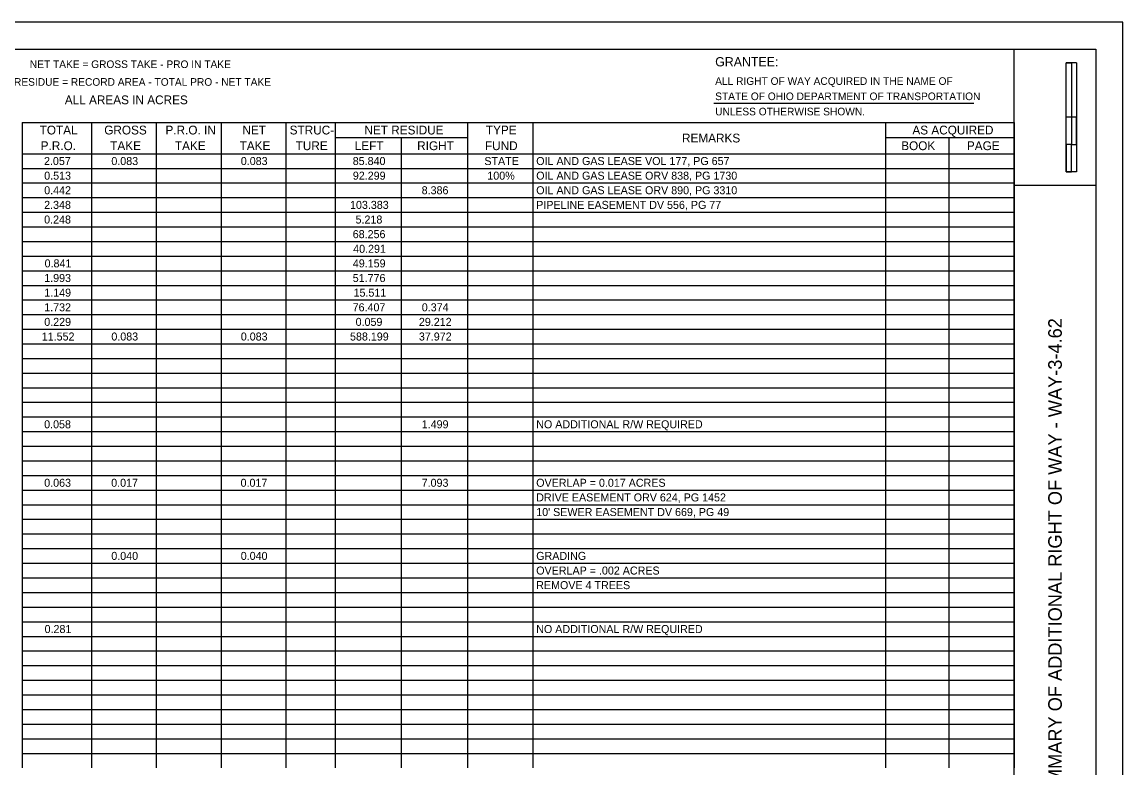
# Model space of a CAD drawing. Extents: x 0 to 34, y 0 to 22.
# Drawn here: x 13.75 to 34, y 8.29 to 22 of the extents above; entities that cross this region are included whole.
import ezdxf

# ---------------------------------------------------------------- set-up
doc = ezdxf.new("R2010")
doc.units = 0
for name, color, linetype in [('Default', 7, 'Continuous'), ('SH_Border', 7, 'Continuous'), ('SH_Cut_Line', 7, 'Continuous'), ('SH_Data', 7, 'Continuous'), ('SH_Text', 7, 'Continuous')]:
    doc.layers.add(name, color=color, linetype=linetype)

msp = doc.modelspace()

# ---------------------------------------------------------------- linework, layer by layer
at = {"layer": 'Default'}
for p, q in [((13.749, 20.156), (16.219, 20.156)), ((13.749, 20.156), (13.749, 15.817)), ((15.029, 20.156), (15.029, 15.817)), ((16.219, 20.156), (30.797, 20.156)), ((16.219, 20.156), (16.219, 15.817)), ((17.409, 20.156), (17.409, 15.817)), ((18.599, 20.156), (18.599, 15.817)), ((19.508, 20.156), (19.508, 15.817)), ((21.94, 20.156), (21.94, 15.817)), ((23.143, 20.156), (23.143, 15.817)), ((29.632, 20.156), (29.632, 15.817)), ((30.797, 20.156), (32, 20.156)), ((32, 20.156), (32, 15.817)), ((19.508, 19.875), (21.94, 19.875)), ((20.724, 19.875), (20.724, 15.817)), ((29.632, 19.875), (30.797, 19.875)), ((30.797, 19.875), (32, 19.875)), ((30.797, 19.875), (30.797, 15.817)), ((13.749, 19.58), (16.219, 19.58)), ((16.219, 19.58), (30.797, 19.58)), ((30.797, 19.58), (32, 19.58)), ((13.749, 19.311), (16.219, 19.311)), ((16.219, 19.311), (30.797, 19.311)), ((30.797, 19.311), (32, 19.311)), ((13.749, 19.043), (16.219, 19.043)), ((16.219, 19.043), (30.797, 19.043)), ((30.797, 19.043), (32, 19.043)), ((13.749, 18.774), (16.219, 18.774)), ((16.219, 18.774), (30.797, 18.774)), ((30.797, 18.774), (32, 18.774)), ((13.749, 18.505), (16.219, 18.505)), ((16.219, 18.505), (30.797, 18.505)), ((30.797, 18.505), (32, 18.505)), ((13.749, 18.236), (16.219, 18.236)), ((16.219, 18.236), (30.797, 18.236)), ((30.797, 18.236), (32, 18.236)), ((13.749, 17.967), (16.219, 17.967)), ((16.219, 17.967), (30.797, 17.967)), ((30.797, 17.967), (32, 17.967)), ((13.749, 17.699), (16.219, 17.699)), ((16.219, 17.699), (30.797, 17.699)), ((30.797, 17.699), (32, 17.699)), ((13.749, 17.43), (16.219, 17.43)), ((16.219, 17.43), (30.797, 17.43)), ((30.797, 17.43), (32, 17.43)), ((13.749, 17.161), (16.219, 17.161)), ((16.219, 17.161), (30.797, 17.161)), ((30.797, 17.161), (32, 17.161)), ((13.749, 16.892), (16.219, 16.892)), ((16.219, 16.892), (30.797, 16.892)), ((30.797, 16.892), (32, 16.892)), ((13.749, 16.624), (16.219, 16.624)), ((16.219, 16.624), (30.797, 16.624)), ((30.797, 16.624), (32, 16.624)), ((13.749, 16.355), (16.219, 16.355)), ((16.219, 16.355), (21.94, 16.355)), ((21.94, 16.355), (30.797, 16.355)), ((30.797, 16.355), (32, 16.355)), ((13.749, 16.086), (16.219, 16.086)), ((16.219, 16.086), (30.797, 16.086)), ((30.797, 16.086), (32, 16.086)), ((13.749, 15.817), (16.219, 15.817)), ((13.749, 15.817), (13.749, 15.548)), ((15.029, 15.817), (15.029, 15.548)), ((16.219, 15.817), (30.797, 15.817)), ((16.219, 15.817), (16.219, 15.548)), ((17.409, 15.817), (17.409, 15.548)), ((18.599, 15.817), (18.599, 15.548)), ((19.508, 15.817), (19.508, 15.548)), ((20.724, 15.817), (20.724, 15.548)), ((21.94, 15.817), (21.94, 15.548)), ((23.143, 15.817), (23.143, 15.548)), ((29.632, 15.817), (29.632, 15.548)), ((30.797, 15.817), (32, 15.817)), ((30.797, 15.817), (30.797, 15.548)), ((32, 15.817), (32, 15.548)), ((13.749, 15.548), (16.219, 15.548)), ((13.749, 15.548), (13.749, 15.28)), ((15.029, 15.548), (15.029, 15.28)), ((16.219, 15.548), (30.797, 15.548)), ((16.219, 15.548), (16.219, 15.28)), ((17.409, 15.548), (17.409, 15.28)), ((18.599, 15.548), (18.599, 15.28)), ((19.508, 15.548), (19.508, 15.28)), ((20.724, 15.548), (20.724, 15.28)), ((21.94, 15.548), (21.94, 15.28)), ((23.143, 15.548), (23.143, 15.28)), ((29.632, 15.548), (29.632, 15.28)), ((30.797, 15.548), (32, 15.548)), ((30.797, 15.548), (30.797, 15.28)), ((32, 15.548), (32, 15.28)), ((13.749, 15.28), (16.219, 15.28)), ((13.749, 15.28), (13.749, 15.011)), ((15.029, 15.28), (15.029, 15.011)), ((16.219, 15.28), (30.797, 15.28)), ((16.219, 15.28), (16.219, 15.011)), ((17.409, 15.28), (17.409, 15.011)), ((18.599, 15.28), (18.599, 15.011)), ((19.508, 15.28), (19.508, 15.011)), ((20.724, 15.28), (20.724, 15.011)), ((21.94, 15.28), (21.94, 15.011)), ((23.143, 15.28), (23.143, 15.011)), ((29.632, 15.28), (29.632, 15.011)), ((30.797, 15.28), (32, 15.28)), ((30.797, 15.28), (30.797, 15.011)), ((32, 15.28), (32, 15.011)), ((13.749, 15.011), (16.219, 15.011)), ((13.749, 15.011), (13.749, 14.473)), ((15.029, 15.011), (15.029, 14.473)), ((16.219, 15.011), (30.797, 15.011)), ((16.219, 15.011), (16.219, 14.473)), ((17.409, 15.011), (17.409, 14.473)), ((18.599, 15.011), (18.599, 14.473)), ((19.508, 15.011), (19.508, 14.473)), ((20.724, 15.011), (20.724, 14.473)), ((21.94, 15.011), (21.94, 14.473)), ((23.143, 15.011), (23.143, 14.473)), ((29.632, 15.011), (29.632, 14.473)), ((30.797, 15.011), (32, 15.011)), ((30.797, 15.011), (30.797, 14.473)), ((32, 15.011), (32, 14.473)), ((13.749, 14.742), (16.219, 14.742)), ((16.219, 14.742), (30.797, 14.742)), ((30.797, 14.742), (32, 14.742)), ((13.749, 14.473), (16.219, 14.473)), ((13.749, 14.473), (13.749, 14.205)), ((15.029, 14.473), (15.029, 14.205)), ((16.219, 14.473), (30.797, 14.473)), ((16.219, 14.473), (16.219, 14.205)), ((17.409, 14.473), (17.409, 14.205)), ((18.599, 14.473), (18.599, 14.205)), ((19.508, 14.473), (19.508, 14.205)), ((20.724, 14.473), (20.724, 14.205)), ((21.94, 14.473), (21.94, 14.205)), ((23.143, 14.473), (23.143, 14.205)), ((29.632, 14.473), (29.632, 14.205)), ((30.797, 14.473), (32, 14.473)), ((30.797, 14.473), (30.797, 14.205)), ((32, 14.473), (32, 14.205)), ((13.749, 14.205), (16.219, 14.205)), ((13.749, 14.205), (13.749, 9.635)), ((15.029, 14.205), (15.029, 9.635)), ((16.219, 14.205), (30.797, 14.205)), ((16.219, 14.205), (16.219, 9.635)), ((17.409, 14.205), (17.409, 9.635)), ((18.599, 14.205), (18.599, 9.635)), ((19.508, 14.205), (19.508, 9.635)), ((20.724, 14.205), (20.724, 9.635)), ((21.94, 14.205), (21.94, 9.635)), ((23.143, 14.205), (23.143, 9.635)), ((29.632, 14.205), (29.632, 9.635)), ((30.797, 14.205), (32, 14.205)), ((30.797, 14.205), (30.797, 9.635)), ((32, 14.205), (32, 9.635)), ((13.749, 13.936), (16.219, 13.936)), ((16.219, 13.936), (30.797, 13.936)), ((30.797, 13.936), (32, 13.936)), ((13.749, 13.667), (16.219, 13.667)), ((16.219, 13.667), (30.797, 13.667)), ((30.797, 13.667), (32, 13.667)), ((13.749, 13.398), (16.219, 13.398)), ((16.219, 13.398), (30.797, 13.398)), ((30.797, 13.398), (32, 13.398)), ((13.749, 13.129), (16.219, 13.129)), ((16.219, 13.129), (30.797, 13.129)), ((30.797, 13.129), (32, 13.129)), ((13.749, 12.861), (16.219, 12.861)), ((16.219, 12.861), (30.797, 12.861)), ((30.797, 12.861), (32, 12.861)), ((13.749, 12.592), (16.219, 12.592)), ((16.219, 12.592), (30.797, 12.592)), ((30.797, 12.592), (32, 12.592)), ((13.749, 12.323), (16.219, 12.323)), ((16.219, 12.323), (30.797, 12.323)), ((30.797, 12.323), (32, 12.323)), ((13.749, 12.054), (16.219, 12.054)), ((16.219, 12.054), (30.797, 12.054)), ((30.797, 12.054), (32, 12.054)), ((13.749, 11.786), (16.219, 11.786)), ((16.219, 11.786), (30.797, 11.786)), ((30.797, 11.786), (32, 11.786)), ((13.749, 11.517), (16.219, 11.517)), ((16.219, 11.517), (30.797, 11.517)), ((30.797, 11.517), (32, 11.517)), ((13.749, 11.248), (16.219, 11.248)), ((16.219, 11.248), (30.797, 11.248)), ((30.797, 11.248), (32, 11.248)), ((13.749, 10.979), (16.219, 10.979)), ((16.219, 10.979), (30.797, 10.979)), ((30.797, 10.979), (32, 10.979)), ((13.749, 10.71), (16.219, 10.71)), ((16.219, 10.71), (30.797, 10.71)), ((30.797, 10.71), (32, 10.71)), ((13.749, 10.442), (16.219, 10.442)), ((16.219, 10.442), (30.797, 10.442)), ((30.797, 10.442), (32, 10.442)), ((13.749, 10.173), (16.219, 10.173)), ((16.219, 10.173), (30.797, 10.173)), ((30.797, 10.173), (32, 10.173)), ((13.749, 9.904), (16.219, 9.904)), ((16.219, 9.904), (30.797, 9.904)), ((30.797, 9.904), (32, 9.904)), ((13.749, 9.635), (16.219, 9.635)), ((13.749, 9.635), (13.749, 9.367)), ((15.029, 9.635), (15.029, 9.367)), ((16.219, 9.635), (30.797, 9.635)), ((16.219, 9.635), (16.219, 9.367)), ((17.409, 9.635), (17.409, 9.367)), ((18.599, 9.635), (18.599, 9.367)), ((19.508, 9.635), (19.508, 9.367)), ((20.724, 9.635), (20.724, 9.367)), ((21.94, 9.635), (21.94, 9.367)), ((23.143, 9.635), (23.143, 9.367)), ((29.632, 9.635), (29.632, 9.367)), ((30.797, 9.635), (32, 9.635)), ((30.797, 9.635), (30.797, 9.367)), ((32, 9.635), (32, 9.367)), ((13.749, 9.367), (16.219, 9.367)), ((13.749, 9.367), (13.749, 9.098)), ((15.029, 9.367), (15.029, 9.098)), ((16.219, 9.367), (30.797, 9.367)), ((16.219, 9.367), (16.219, 9.098)), ((17.409, 9.367), (17.409, 9.098)), ((18.599, 9.367), (18.599, 9.098)), ((19.508, 9.367), (19.508, 9.098)), ((20.724, 9.367), (20.724, 9.098)), ((21.94, 9.367), (21.94, 9.098)), ((23.143, 9.367), (23.143, 9.098)), ((29.632, 9.367), (29.632, 9.098)), ((30.797, 9.367), (32, 9.367)), ((30.797, 9.367), (30.797, 9.098)), ((32, 9.367), (32, 9.098)), ((13.749, 9.098), (16.219, 9.098)), ((13.749, 9.098), (13.749, 8.291)), ((15.029, 9.098), (15.029, 8.291)), ((16.219, 9.098), (30.797, 9.098)), ((16.219, 9.098), (16.219, 8.291)), ((17.409, 9.098), (17.409, 8.291)), ((18.599, 9.098), (18.599, 8.291)), ((19.508, 9.098), (19.508, 8.291)), ((20.724, 9.098), (20.724, 8.291)), ((21.94, 9.098), (21.94, 8.291)), ((23.143, 9.098), (23.143, 8.291)), ((29.632, 9.098), (29.632, 8.291)), ((30.797, 9.098), (32, 9.098)), ((30.797, 9.098), (30.797, 8.291)), ((32, 9.098), (32, 8.291)), ((13.749, 8.829), (16.219, 8.829)), ((16.219, 8.829), (30.797, 8.829)), ((30.797, 8.829), (32, 8.829)), ((13.749, 8.56), (16.219, 8.56)), ((16.219, 8.56), (30.797, 8.56)), ((30.797, 8.56), (32, 8.56))]:
    msp.add_line(p, q, dxfattribs=at)
at = {"layer": 'SH_Border'}
for p, q in [((32, 0.5), (32, 21.5)), ((32, 19), (33.5, 19))]:
    msp.add_line(p, q, dxfattribs=at)
msp.add_lwpolyline([(1.5, 21.5), (33.5, 21.5), (33.5, 0.5), (1.5, 0.5)], close=True, dxfattribs=at)
at = {"layer": 'SH_Cut_Line'}
msp.add_lwpolyline([(0, 0), (34, 0), (34, 22), (0, 22)], close=True, dxfattribs=at)
at = {"layer": 'SH_Data'}
for p, q in [((32.957, 19.25), (32.957, 21.25)), ((33.144, 21.25), (32.957, 21.25)), ((32.957, 20.25), (32.957, 21.25)), ((32.957, 21.25), (33.05, 21.25)), ((33.05, 21.25), (33.051, 21.25)), ((33.051, 21.25), (33.051, 20.25)), ((33.144, 21.25), (33.144, 19.25)), ((33.051, 20.25), (32.957, 20.25)), ((33.143, 20.25), (33.05, 20.25)), ((33.05, 20.25), (33.05, 19.75)), ((33.143, 19.75), (33.143, 20.25)), ((33.05, 19.75), (32.957, 19.75)), ((32.957, 19.75), (32.957, 19.25)), ((33.05, 19.75), (33.143, 19.75)), ((33.05, 19.25), (33.05, 19.75)), ((33.144, 19.25), (32.957, 19.25)), ((32.957, 19.25), (33.05, 19.25))]:
    msp.add_line(p, q, dxfattribs=at)
at = {"layer": 'SH_Text'}
msp.add_line((26.477, 20.508), (31.257, 20.508), dxfattribs=at)

# ---------------------------------------------------------------- texts
at = {"layer": 'Default'}
for s, height, p in [('ALL AREAS IN ACRES', 0.16191, (14.536, 20.489)), ('TOTAL', 0.1619, (14.073, 19.934)), ('GROSS', 0.1619, (15.261, 19.934)), ('P.R.O. IN', 0.1619, (16.387, 19.934)), ('NET', 0.1619, (17.803, 19.934)), ('STRUC-', 0.1619, (18.672, 19.934)), ('NET RESIDUE', 0.16191, (20.047, 19.934)), ('TYPE', 0.1619, (22.281, 19.934)), ('AS ACQUIRED', 0.16191, (30.126, 19.934)), ('REMARKS', 0.1619, (25.889, 19.787)), ('P.R.O.', 0.1619, (14.092, 19.646)), ('TAKE', 0.1619, (15.371, 19.646)), ('TAKE', 0.1619, (16.561, 19.646)), ('TAKE', 0.1619, (17.751, 19.646)), ('TURE', 0.1619, (18.782, 19.646)), ('LEFT', 0.1619, (19.869, 19.646)), ('RIGHT', 0.1619, (21.017, 19.646)), ('FUND', 0.1619, (22.264, 19.646)), ('BOOK', 0.1619, (29.921, 19.646)), ('PAGE', 0.1619, (31.129, 19.646)), ('2.057', 0.1472, (14.153, 19.372)), ('0.083', 0.1472, (15.392, 19.372)), ('0.083', 0.1472, (17.773, 19.372)), ('85.840', 0.1472, (19.832, 19.372)), ('STATE', 0.1472, (22.253, 19.372)), ('OIL AND GAS LEASE VOL 177, PG 657', 0.14719, (23.207, 19.372)), ('0.513', 0.1472, (14.157, 19.103)), ('92.299', 0.1472, (19.834, 19.103)), ('100%', 0.1472, (22.308, 19.103)), ('OIL AND GAS LEASE ORV 838, PG 1730', 0.14719, (23.207, 19.103)), ('0.442', 0.1472, (14.157, 18.835)), ('8.386', 0.1472, (21.1, 18.835)), ('OIL AND GAS LEASE ORV 890, PG 3310', 0.14719, (23.207, 18.835)), ('2.348', 0.1472, (14.156, 18.566)), ('103.383', 0.1472, (19.782, 18.566)), ('PIPELINE EASEMENT DV 556, PG 77', 0.14719, (23.207, 18.566)), ('0.248', 0.1472, (14.156, 18.297)), ('5.218', 0.1472, (19.884, 18.297)), ('68.256', 0.1472, (19.832, 18.028)), ('40.291', 0.1472, (19.84, 17.759)), ('0.841', 0.1472, (14.164, 17.491)), ('49.159', 0.1472, (19.834, 17.491)), ('1.993', 0.1472, (14.157, 17.222)), ('51.776', 0.1472, (19.832, 17.222)), ('1.149', 0.1472, (14.158, 16.953)), ('15.511', 0.1472, (19.847, 16.953)), ('1.732', 0.1472, (14.157, 16.684)), ('76.407', 0.1472, (19.83, 16.684)), ('0.374', 0.1472, (21.102, 16.684)), ('0.229', 0.1472, (14.158, 16.416)), ('0.059', 0.1472, (19.885, 16.416)), ('29.212', 0.1472, (21.049, 16.416)), ('11.552', 0.1472, (14.112, 16.147)), ('0.083', 0.1472, (15.392, 16.147)), ('0.083', 0.1472, (17.773, 16.147)), ('588.199', 0.1472, (19.782, 16.147)), ('37.972', 0.1472, (21.049, 16.147)), ('0.058', 0.1472, (14.156, 14.534)), ('1.499', 0.1472, (21.101, 14.534)), ('NO ADDITIONAL R/W REQUIRED', 0.14719, (23.207, 14.534)), ('0.063', 0.1472, (14.157, 13.459)), ('0.017', 0.1472, (15.389, 13.459)), ('0.017', 0.1472, (17.769, 13.459)), ('7.093', 0.1472, (21.1, 13.459)), ('OVERLAP = 0.017 ACRES', 0.14719, (23.207, 13.459)), ('DRIVE EASEMENT ORV 624, PG 1452', 0.14719, (23.207, 13.19)), ("10' SEWER EASEMENT DV 669, PG 49", 0.14719, (23.207, 12.921)), ('0.040', 0.1472, (15.391, 12.115)), ('0.040', 0.1472, (17.772, 12.115)), ('GRADING', 0.1472, (23.207, 12.115)), ('OVERLAP = .002 ACRES', 0.14719, (23.207, 11.846)), ('REMOVE 4 TREES', 0.14719, (23.207, 11.578)), ('0.281', 0.1472, (14.164, 10.771)), ('NO ADDITIONAL R/W REQUIRED', 0.14719, (23.207, 10.771))]:
    msp.add_text(s, height=height, dxfattribs=at).set_placement(p)
at = {"layer": 'SH_Data'}
msp.add_text('SUMMARY OF ADDITIONAL RIGHT OF WAY - WAY-3-4.62', height=0.25, rotation=90, dxfattribs=at).set_placement((32.875, 7.531))
at = {"layer": 'SH_Text'}
for s, height, p in [('NET TAKE = GROSS TAKE - PRO IN TAKE', 0.14, (13.892, 21.155)), ('GRANTEE:', 0.17, (26.499, 21.185)), ('NET RESIDUE = RECORD AREA - TOTAL PRO - NET TAKE', 0.14, (13.175, 20.829)), ('ALL RIGHT OF WAY ACQUIRED IN THE NAME OF', 0.14, (26.499, 20.845)), ('STATE OF OHIO DEPARTMENT OF TRANSPORTATION     ', 0.14, (26.499, 20.565)), ('UNLESS OTHERWISE SHOWN.', 0.14, (26.499, 20.285))]:
    msp.add_text(s, height=height, dxfattribs=at).set_placement(p)

doc.saveas('drawing.dxf')
